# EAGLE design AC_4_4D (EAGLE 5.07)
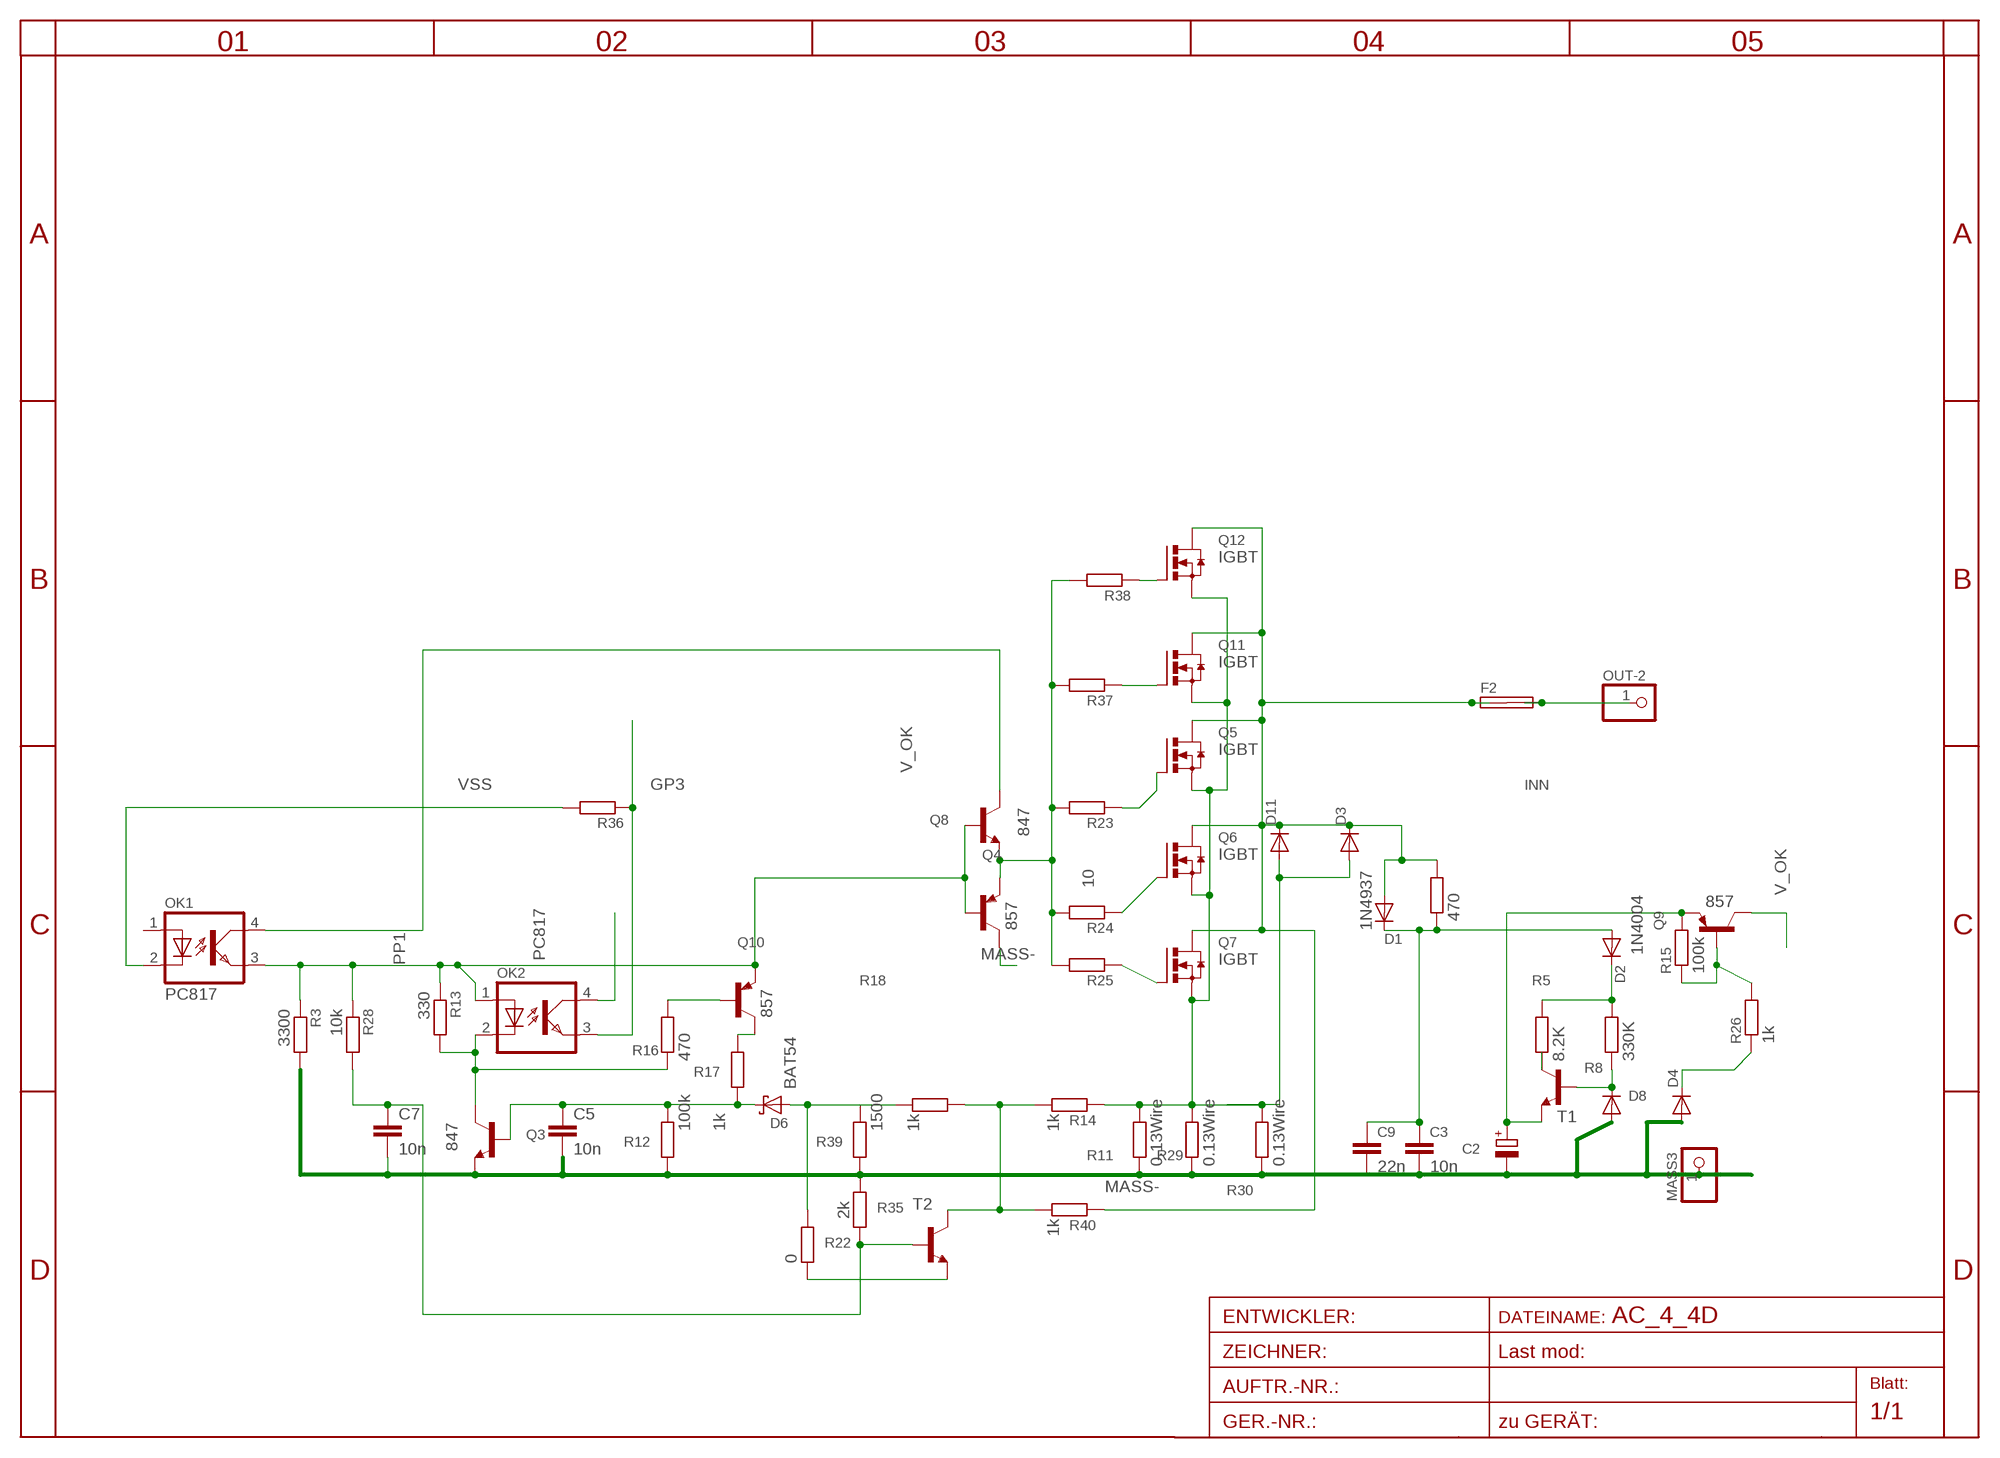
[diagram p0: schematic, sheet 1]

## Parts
C2  CPOL-EUE2.5-5  [E2,5-5]
C3  10n  C-EU025_050-050X075  [C025_050-050X075]
C5  10n  C-EUC0805  [C0805]
C7  10n  C-EUC0805  [C0805]
C9  22n  C-EU102-043X133  [C102-043X133]
D1  1N4937  1N4004DO41-10  [DO41-10]
D2  1N4004  [DO41-20]
D3  DIODE-SMC  [SMC]
D4  DIODE-MINIMELF  [MINIMELF]
D6  BAT54  [SOT23]
D8  DIODE-MINIMELF  [MINIMELF]
D11  DIODE-SMC  [SMC]
F2  SHK20L7MM5  [7MM5]
MASS3  PINHD-1X13MM2  [1X3MM2]
OK1  PC817  [DIL04]
OK2  PC817  [DIL04]
OUT-2  PINHD-1X13MM2  [1X3MM2]
Q3  847  BC846ALT1SMD  [SOT23]
Q4  857  BC857ALT1SMD  [SOT23-BEC]
Q5  IGBT  N-HEXFET_DPAK-  [TO252]
Q6  IGBT  N-HEXFET_DPAK-  [TO252]
Q7  IGBT  N-HEXFET_DPAK-  [TO252]
Q8  847  BC846ALT1SMD  [SOT23]
Q9  857  BC857ALT1SMD  [SOT23-BEC]
Q10  857  BC857ALT1SMD  [SOT23-BEC]
Q11  IGBT  N-HEXFET_DPAK-  [TO252]
Q12  IGBT  N-HEXFET_DPAK-  [TO252]
R3  3300  R-EU_R0805  [R0805]
R5  8.2K  R-EU_0204/5  [0204/5]
R8  330K  R-EU_0204/5  [0204/5]
R11  0.13Wire  R-EU_0204/5  [0204/5]
R12  100k  R-EU_R0805  [R0805]
R13  330  R-EU_R1206  [R1206]
R14  1k  R-EU_R0805  [R0805]
R15  100k  R-EU_R0805  [R0805]
R16  470  R-EU_R0805  [R0805]
R17  1k  R-EU_R1206  [R1206]
R18  1k  R-EU_R0805  [R0805]
R22  0  R-EU_R0805  [R0805]
R23  R-EU_0207/12  [0207/12]
R24  R-EU_0207/15  [0207/15]
R25  10  R-EU_0207/12  [0207/12]
R26  1k  R-EU_R0805  [R0805]
R27  470  R-EU_0207/10  [0207/10]
R28  10k  R-EU_R0805  [R0805]
R29  0.13Wire  R-EU_0204/5  [0204/5]
R30  0.13Wire  R-EU_0204/5  [0204/5]
R35  2k  R-EU_R0805  [R0805]
R36  R-EU_0207/12  [0207/12]
R37  R-EU_0207/15  [0207/15]
R38  R-EU_0207/10  [0207/10]
R39  1500  R-EU_R0805  [R0805]
R40  1k  R-EU_R1206  [R1206]
T1  -NPN-TO92-EBC  [TO92-EBC]
T2  -NPN-TO92-EBC  [TO92-EBC]

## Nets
D1: D1.A D3.C D11.C F2.1A F2.1B Q5.3(D) Q6.3(D) Q7.3(D) Q11.3(D) Q12.3(D) R27.2 R40.2
GP3: OK2.3(EMIT) R36.1
INN: F2.2A F2.2B OUT-2.1
MASS-: C2.- C3.3 C5.2 C7.2 C9.2 D4.A D8.A MASS3.1 Q3.2(E) Q4.C R3.2 R11.1 R12.2 R29.1 R30.1 R35.2 R39.2
N$2: C3.1 C9.1 D1.C D2.A R27.1
N$11: C5.1 D6.3(C) Q3.1(B) R12.1 R17.2
N$12: OK2.2(C) Q3.3(C) R13.2 R16.1
N$14: R14.1 R18.2 R40.1 T2.C
N$16: Q10.B R16.2
N$17: Q10.C R17.1
N$20: D2.C R5.2 R8.2
N$25: Q12.1(G) R38.1
N$26: Q6.1(G) R24.1
N$27: Q5.1(G) R23.1
N$34: R5.1 T1.C
N$35: D4.C R26.1
N$36: D8.C R8.1 T1.B
N$37: Q4.E Q8.2(E) R23.2 R24.2 R25.2 R37.2 R38.2
N$38: C2.+ Q9.E R15.2 T1.E
N$40: C7.1 R28.2 R35.1 T2.B
N$41: Q9.B R15.1 R26.2
N$45: R22.1 T2.E
N$46: Q11.1(G) R37.1
N$47: Q7.1(G) R25.1
N$48: D6.1(A) R18.1 R22.2 R39.1
PP1: OK1.3(EMIT) OK2.1(A) Q4.B Q8.1(B) Q10.E R3.1 R13.1 R28.1
SRC1: D3.A D11.A Q5.2(S) Q6.2(S) Q7.2(S) Q11.2(S) Q12.2(S) R11.2 R14.2 R29.2 R30.2
V_OK: OK1.4(COL) Q8.3(C) Q9.C
VDD: OK2.4(COL)
VSS: OK1.2(C) R36.2
Unconnected: OK1.1(A)

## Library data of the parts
C2 = rcl-2:CPOL-EU: POLARIZED CAPACITOR, European symbol
C3 C9 = rcl-2:C-EU: CAPACITOR, European symbol
C5 C7 = rcl:C-EU: CAPACITOR, European symbol
D1 D2 = diode:1N4004: DIODE
D3 D4 D8 D11 = diode:DIODE-: DIODE
D6 = diode:BAT54: Schottky Diodes
F2 = fuse:SHK20L: FUSE HOLDER 5 x 20 mm, SH contact, SHH1 Schukat, E1073 Buerklin
MASS3 OUT-2 = pinhead:PINHD-1X1: PIN HEADER
OK1 OK2 = optocoupler:PC817: SHARP OPTO COUPLER
Q3 Q8 = transistor-npn:BC846*: NPN Transistor
Q4 Q9 Q10 = transistor-pnp:BC857*: PNP Transistror
Q5-Q7 Q11 Q12 = transistor-power:N-HEXFET_?-*: HEXFET® Power MOSFET
R3 R5 R8 R11-R18 R22-R30 R35-R40 = rcl-2:R-EU_: RESISTOR, European symbol
T1 T2 = transistor-neu-to92:*-NPN-: NPN Transistror

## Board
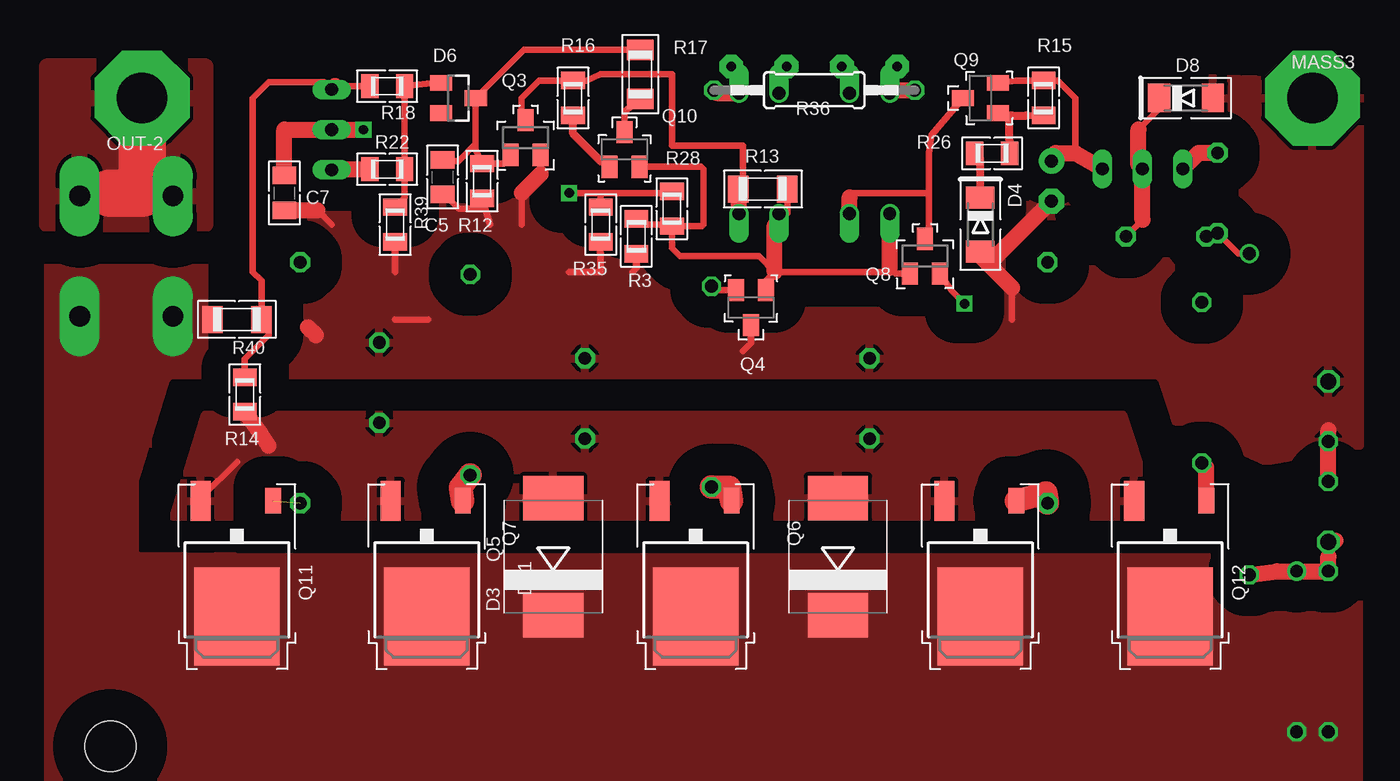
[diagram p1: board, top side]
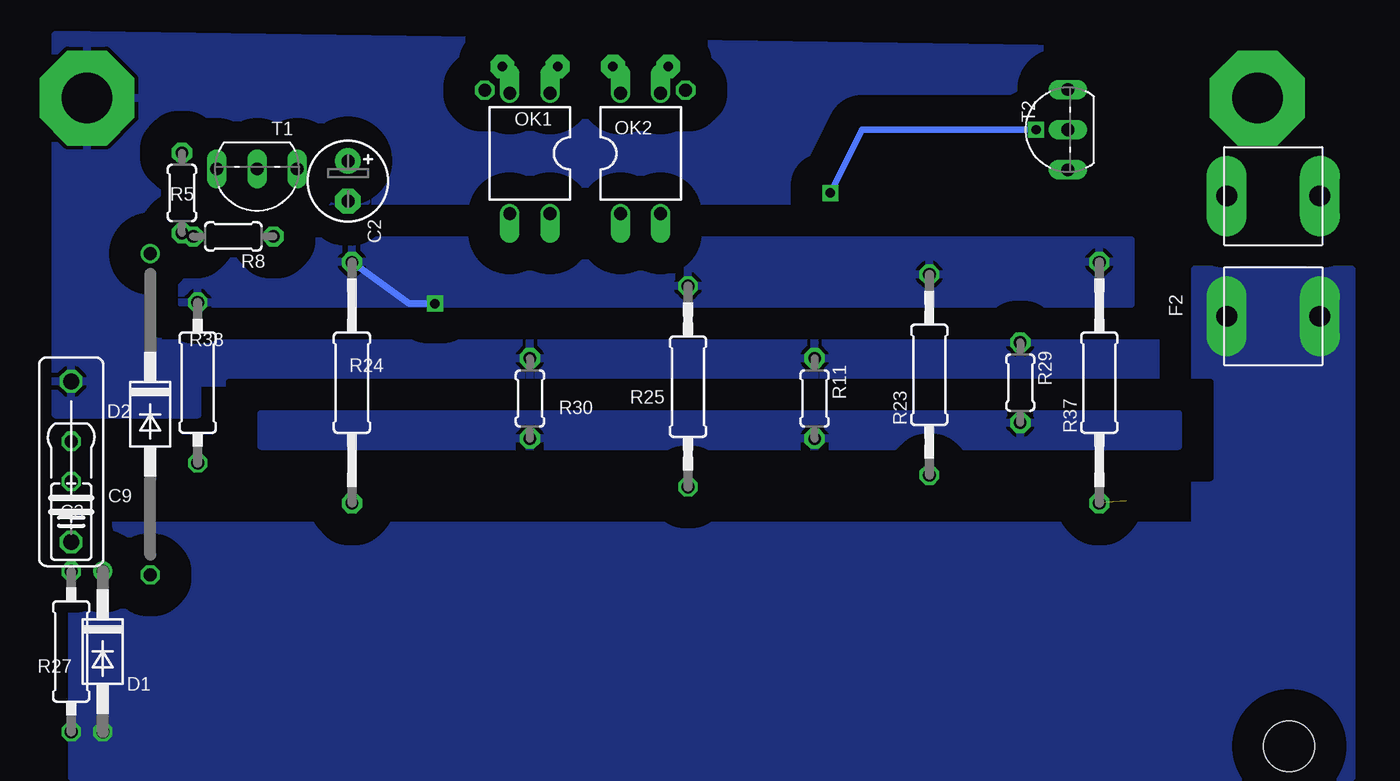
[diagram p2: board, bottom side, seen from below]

No outline drawn. Coordinates in mm, seen from the top.
Copper layers (1*16): Top 0.035mm / dielectric 1.5mm / Bottom 0.035mm
Design rules "default *": minimum track width 12mil, minimum drill 24mil, track to track 8mil, track to pad 8mil, pad to pad 8mil, via to via 8mil, smd to smd 8mil, copper to edge 40mil, drill to drill 8mil, minimum pad ring 8mil, minimum via ring 8mil, stop-mask expansion 4mil, vias tented up to drill 0mil, thermal gap 10mil
Holes 3.2 mm at 5,96 4,4 197,95 196,3

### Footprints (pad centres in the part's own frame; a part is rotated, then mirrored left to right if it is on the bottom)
E2,5-5 = drill 0.813 pad 1.6 round: + -1.27,0 | drill 0.813 pad 1.6 octagon: - 1.27,0
C025_050-050X075 = drill 0.813 octagon: 1 -3.81,0; 2 0,0; 3 2.54,0
C0805 = smd 1.1 x 1.5: 1 -1.1,0; 2 1.1,0
C102-043X133 = drill 1.016 octagon: 1 -5.08,0; 2 5.08,0
DO41-10 = drill 0.8 octagon: A 5.08,0 | drill 0.8 round: C -5.08,0
DO41-20 = drill 0.8 octagon: A 10.16,0 | drill 0.8 round: C -10.16,0
SMC = smd 2.8 x 3.8: A 3.7,0; C -3.7,0
MINIMELF = smd 1.4 x 1.8: A 1.7,0; C -1.7,0
SOT23 = smd 1 x 1.4: 1 -0.95,-1.1; 2 0.95,-1.1; 3 0,1.1
7MM5 = drill 1.3 pad 2.54 long: 1A -3.8,2.94; 1B -3.8,-2.94; 2A 3.8,2.94; 2B 3.8,-2.94
1X3MM2 = drill 3.2 pad 6 octagon: 1 0,0
DIL04 = drill 0.813 offset: 1 -1.27,-3.81; 2 1.27,-3.81; 3 1.27,3.81; 4 -1.27,3.81
SOT23-BEC = smd 1 x 1.4: B -0.95,-1.1; C 0,1.1; E 0.95,-1.1
TO252 = smd 1 x 1.6: 1 -2.28,-3.53 | smd 1.27 x 2.54: 2 2.28,-3.53 | smd 5.4 x 6.2: 3 0,3.77
R0805 = smd 1.1 x 1.5: 1 -1.1,0; 2 1.1,0
0204/5 = drill 0.8 pad 1.27 octagon: 1 -2.54,0; 2 2.54,0
R1206 = smd 1.3 x 1.7: 1 -1.55,0; 2 1.55,0
0207/12 = drill 0.813 octagon: 1 -6.35,0; 2 6.35,0
0207/15 = drill 0.8 pad 1.27 octagon: 1 -7.62,0; 2 7.62,0
0207/10 = drill 0.813 octagon: 1 -5.08,0; 2 5.08,0
TO92-EBC = drill 0.813 long: B 0,-1.27; C 2.54,-1.27; E -2.54,-1.27

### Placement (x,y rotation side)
C2  63.5,39.75 270 bottom
C3  81,20.75 90 bottom
C5  25,40 270 top
C7  15,39 270 top
C9  81,22 90 bottom
D1  79,10 270 bottom
D2  76,25 270 bottom
D3  32,16 90 top
D4  59,37 270 top
D6  26,45 270 top
D8  72,45 0 top
D11  50,16 90 top
F2  5,35 90 bottom
MASS3  80,45 0 top
OK1  52,41.5 180 bottom
OK2  45,41.5 0 bottom
OUT-2  6,45 180 top
Q3  30.25,42.5 0 top
Q4  44.5,31.75 180 top
Q5  24,16 180 top
Q6  59,16 180 top
Q7  41,16 180 top
Q8  55.5,35 0 top
Q9  59,45 90 top
Q10  36.5,41.75 0 top
Q11  12,16 180 top
Q12  71,16 180 top
R3  37.25,36.25 270 top
R5  74,39 270 bottom
R8  70.75,36.25 180 bottom
R11  34,26 270 bottom
R12  27.5,39.75 270 top
R13  45.25,39.25 180 top
R14  12.5,26.25 270 top
R15  63,45 90 top
R16  33.25,45 270 top
R17  37.5,46.5 90 top
R18  21.5,45.75 180 top
R22  21.5,40.5 0 top
R23  26.75,27.5 90 bottom
R24  63.25,27 90 bottom
R25  42,26.75 90 bottom
R26  59.75,41.5 0 top
R27  81,10 270 bottom
R28  39.5,38 90 top
R29  21,27 270 bottom
R30  52,26 270 bottom
R35  35,37 270 top
R36  48.5,45.5 0 top
R37  16,27 90 bottom
R38  73,27 90 bottom
R39  22,37 270 top
R40  12,31 180 top
T1  69.25,39.25 180 bottom
T2  19.25,43 90 bottom

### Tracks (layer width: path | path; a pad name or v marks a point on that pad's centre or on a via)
D1
  pour Top (isolate 2, rank 2, no thermals): 83,0 0,0 0,35 10,35 10,17 12,16 83,16
  pour Bottom (isolate 2, rank 2, no thermals): 81,2 0,2 0,34.18 10,34.18 10,18 81,18
GP3
  Top 1: OK2.3 42.34,45.31 R36.1
INN
  Top 1: F2.2A F2.2B 3.26,39 4,39
  Top 3: OUT-2.1 6,39 4,39
  pour Top: 10,37 0,37 0,47 10,47
MASS-
  Top 0.406: 22,31 24.1,31 | D4.A 59,35 | 61,33 61,31 | C5.2 25.1,38.9 26,38 27.35,38 R12.2 28,37 | 33,34 35,34 R35.2 | 17.1,37.9 18,37 | Q4.C 44.5,29.5 44,29 | R3.2 37.25,34.25 37,34 | 31.2,40.2 Q3.2 | 30,37 30,39 | 22,34 R39.2
  Top 1: 17,30 16.5,30.5 | 59,35 59.5,34.5 | 59.5,34.5 61,33 | C7.2 17.1,37.9 | 30,39 31.2,40.2 | C2.- 63.48,38.48 59.5,34.5 | 81,21 81,24
  pour Top (isolate 2, rank 3): 83,23 77,22 68,26 15,26 15,48 83,46
  pour Bottom (isolate 2, rank 3): 82,25 73,25 73,27 11,27 11,48 82,49
N$2
  Top 0.5: 81,16 C9.1 C3.1
  Top 1: 81,16 R27.1 D1.C 77.76,15.08 D2.A | C9.1 81.46,17
N$11
  Top 0.406: 27.1,42.1 D6.3 30.15,48.05 R17.2 | 27.1,42.1 26,41 25.1,41 C5.1 | 27.1,42.1 27.1,41.75 R12.1 28.85,40.85 Q3.1
N$12
  Top 0.406: R13.2 44,39.05 44,42 39.5,42 39.5,46.5 35,46.5 34.1,46.1 R16.1 31.1,46.1 30,45 30,43.85 Q3.3 | 43.7,37.22 OK2.2
  Top 1: R13.2 43.7,37.22
N$14
  Top 0.406: R14.1 12.5,28.5 14,30 14,30.55 R40.1 13.55,33.45 13,34 13,45 14,46 17.52,46 T2.C | 18.19,45.75 R18.2
  Top 1: T2.C 18.19,45.75
N$16
  Top 0.5: R16.2 33.25,42.75 35,41 35.2,41 Q10.B
N$17
  Top 0.406: Q10.C 36.5,44.15 R17.1
N$20
  Top 0.406: D2.C 75.3,35.16 R5.2 73.5,36.46 R8.2
N$21  (via drill 0.6 pad 1.5)
  other vias: 43.25,47
N$22  (via drill 0.6 pad 1.5)
  other vias: 46.75,47
N$23  (via drill 0.6 pad 1.5)
  other vias: 50.25,47
N$24  (via drill 0.6 pad 1.5)
  other vias: 53.75,47
N$25
  Top 1: Q12.1 73.28,21.64 R38.1
N$26
  Top 1.5: Q6.1 63.15,20.03 R24.1
N$27
  Top 1.5: R23.1 26.13,20.38 Q5.1
N$34
  Top 1: R5.1 72.81,41.54 T1.C
N$35
  Top 0.5: D4.C 59,41.15 R26.1
N$36
  Top 0.406: D8.C 70.3,44.3 69,43 | T1.B 69,40.77 | R8.1 69.25,37.29
  Top 1: 69,40.77 69,43 | 69.25,37.29 T1.B
N$37  (via drill 0.6)
  Top 0.406: Q8.2 57.2,32.8 v58,32 | Q4.E 42.25,32.85 R25.2
  Bottom 0.406: v58,32 59.63,32 R24.2 | R25.2 42,32
  pour Bottom (isolate 2, rank 2): 74,32 14,32 14,36 74,36
N$38
  Top 0.406: C2.+ 63.75,41.52 | 65,41.52 65,45 63.9,46.1 R15.2 61.25,46.1 Q9.E
  Top 1: 63.75,41.52 65,41.52 T1.E
N$40  (via drill 0.6)
  Top 0.406: 35,39 39.6,39 R28.2 | v33,39 35,39 | 35,39 R35.1
  Top 1: C7.1 15,43 T2.B v20,43
  Bottom 0.406: v20,43 31,43 v33,39
  Bottom 1: T2.B 17.65,43
N$41
  Top 0.406: R26.2 60.85,42.3 | 61.9,43.9 R15.1
  Top 0.5: 61,43.9 61.9,43.9 | 61,43.9 60.25,43.9 Q9.B | 60.85,42.3 60.85,43.75 61,43.9
N$45
  Top 1: R22.1 18.02,40.5 T2.E
N$46  (1 unrouted)
N$47
  Top 1.5: R25.1 43.13,20.38 Q7.1
N$48
  Top 0.406: D6.1 24.85,46 R18.1 R22.2 22.6,38.7 R39.1
PP1
  Top 0.406: 46,34 53,34 53.27,34.27 53.64,33.9 Q8.1 | 46,36.92 OK2.1 46.8,37.72 R13.1 | Q4.B 45.45,33.45 46,34 | R28.1 41.4,36.9 41.5,37 41.5,40.5 41.35,40.65 Q10.E | R28.1 39.5,35.5 40,35 45,35 46,34 | R28.1 39.1,36.9 39,37 37.6,37 R3.1
  Top 1: 53.27,34.27 OK1.3 | 46,34 46,36.92
SRC1
  Top 0.406: Q11.2 9.72,19.72 12,22
  Top 1: R14.2 13.5,23.75 14,23
  pour Top (isolate 2): 69,18.5 8,18.5 10,25 68,25 69,22
  pour Bottom (isolate 2): 69,23 11,23 11,25 69,25
V_OK
  Top 0.406: Q9.C 55.9,42.65 55.75,41.5 55.75,39 | 55.75,39 55.75,36.35 Q8.3 | 50.73,38.73 51,39 55.75,39
  Top 1: OK1.4 50.73,38.73
VSS
  Top 1: R36.2 53.46,45.5 OK1.2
